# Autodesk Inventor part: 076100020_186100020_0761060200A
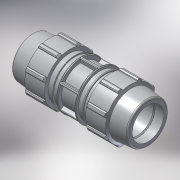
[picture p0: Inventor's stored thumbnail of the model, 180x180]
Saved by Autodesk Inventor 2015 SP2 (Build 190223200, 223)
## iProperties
Created: 2017-02
Part Number: 076100020_186100020_0761060200A
Material: PVC-Piping
Description: PLASSON REPAIR COUPLER 20
Document SubType Name: Modeling
Designer: KIM
Mass: 8658.36 g
Surface Area: 5623.3 cm^2
Volume: 6184.54 cm^3
Density: 1.4 g/cm^3
Appearance: Smooth - White
Author: KIM
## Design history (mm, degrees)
derived "07610.ipt"
feature "Solid1::07610.ipt"
tag "TaggingFeature1"
body "Solid1"
other parameters: "d1" = 122, "d4" = 10.16667, "d5" = 17.42857, "d7" = 48, "d8" = 36, "d9" = 17.42857, "d11" = 3.48571, "d12" = 38.4, "d13" = 120 deg, "d15" = 12 deg, "d16" = 43.2, "d18" = 1, "d19" = 35 deg, "d20" = 17.5 deg, "d21" = 44.64, "d23" = 0, "d25" = 360 deg, "d27" = 0.96, "d33" = 0.4, "d34" = 2.4, "d36" = 0, "d37" = 0.4, "d38" = 0.4, "d40" = 360 deg, "d42" = 21.96, "d43" = 1.44, "d46" = 0.6, "d50" = 3.83429, "d51" = 38.4, "E_" = 48, "H_" = 122, "l_" = 78, "d49" = 11.15429
